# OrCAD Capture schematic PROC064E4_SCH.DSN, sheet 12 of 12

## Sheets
12 05. CAN/RS485/BORD ID INTERFACE: size C; title: CAN/RS485/BOARD ID INTERFACE
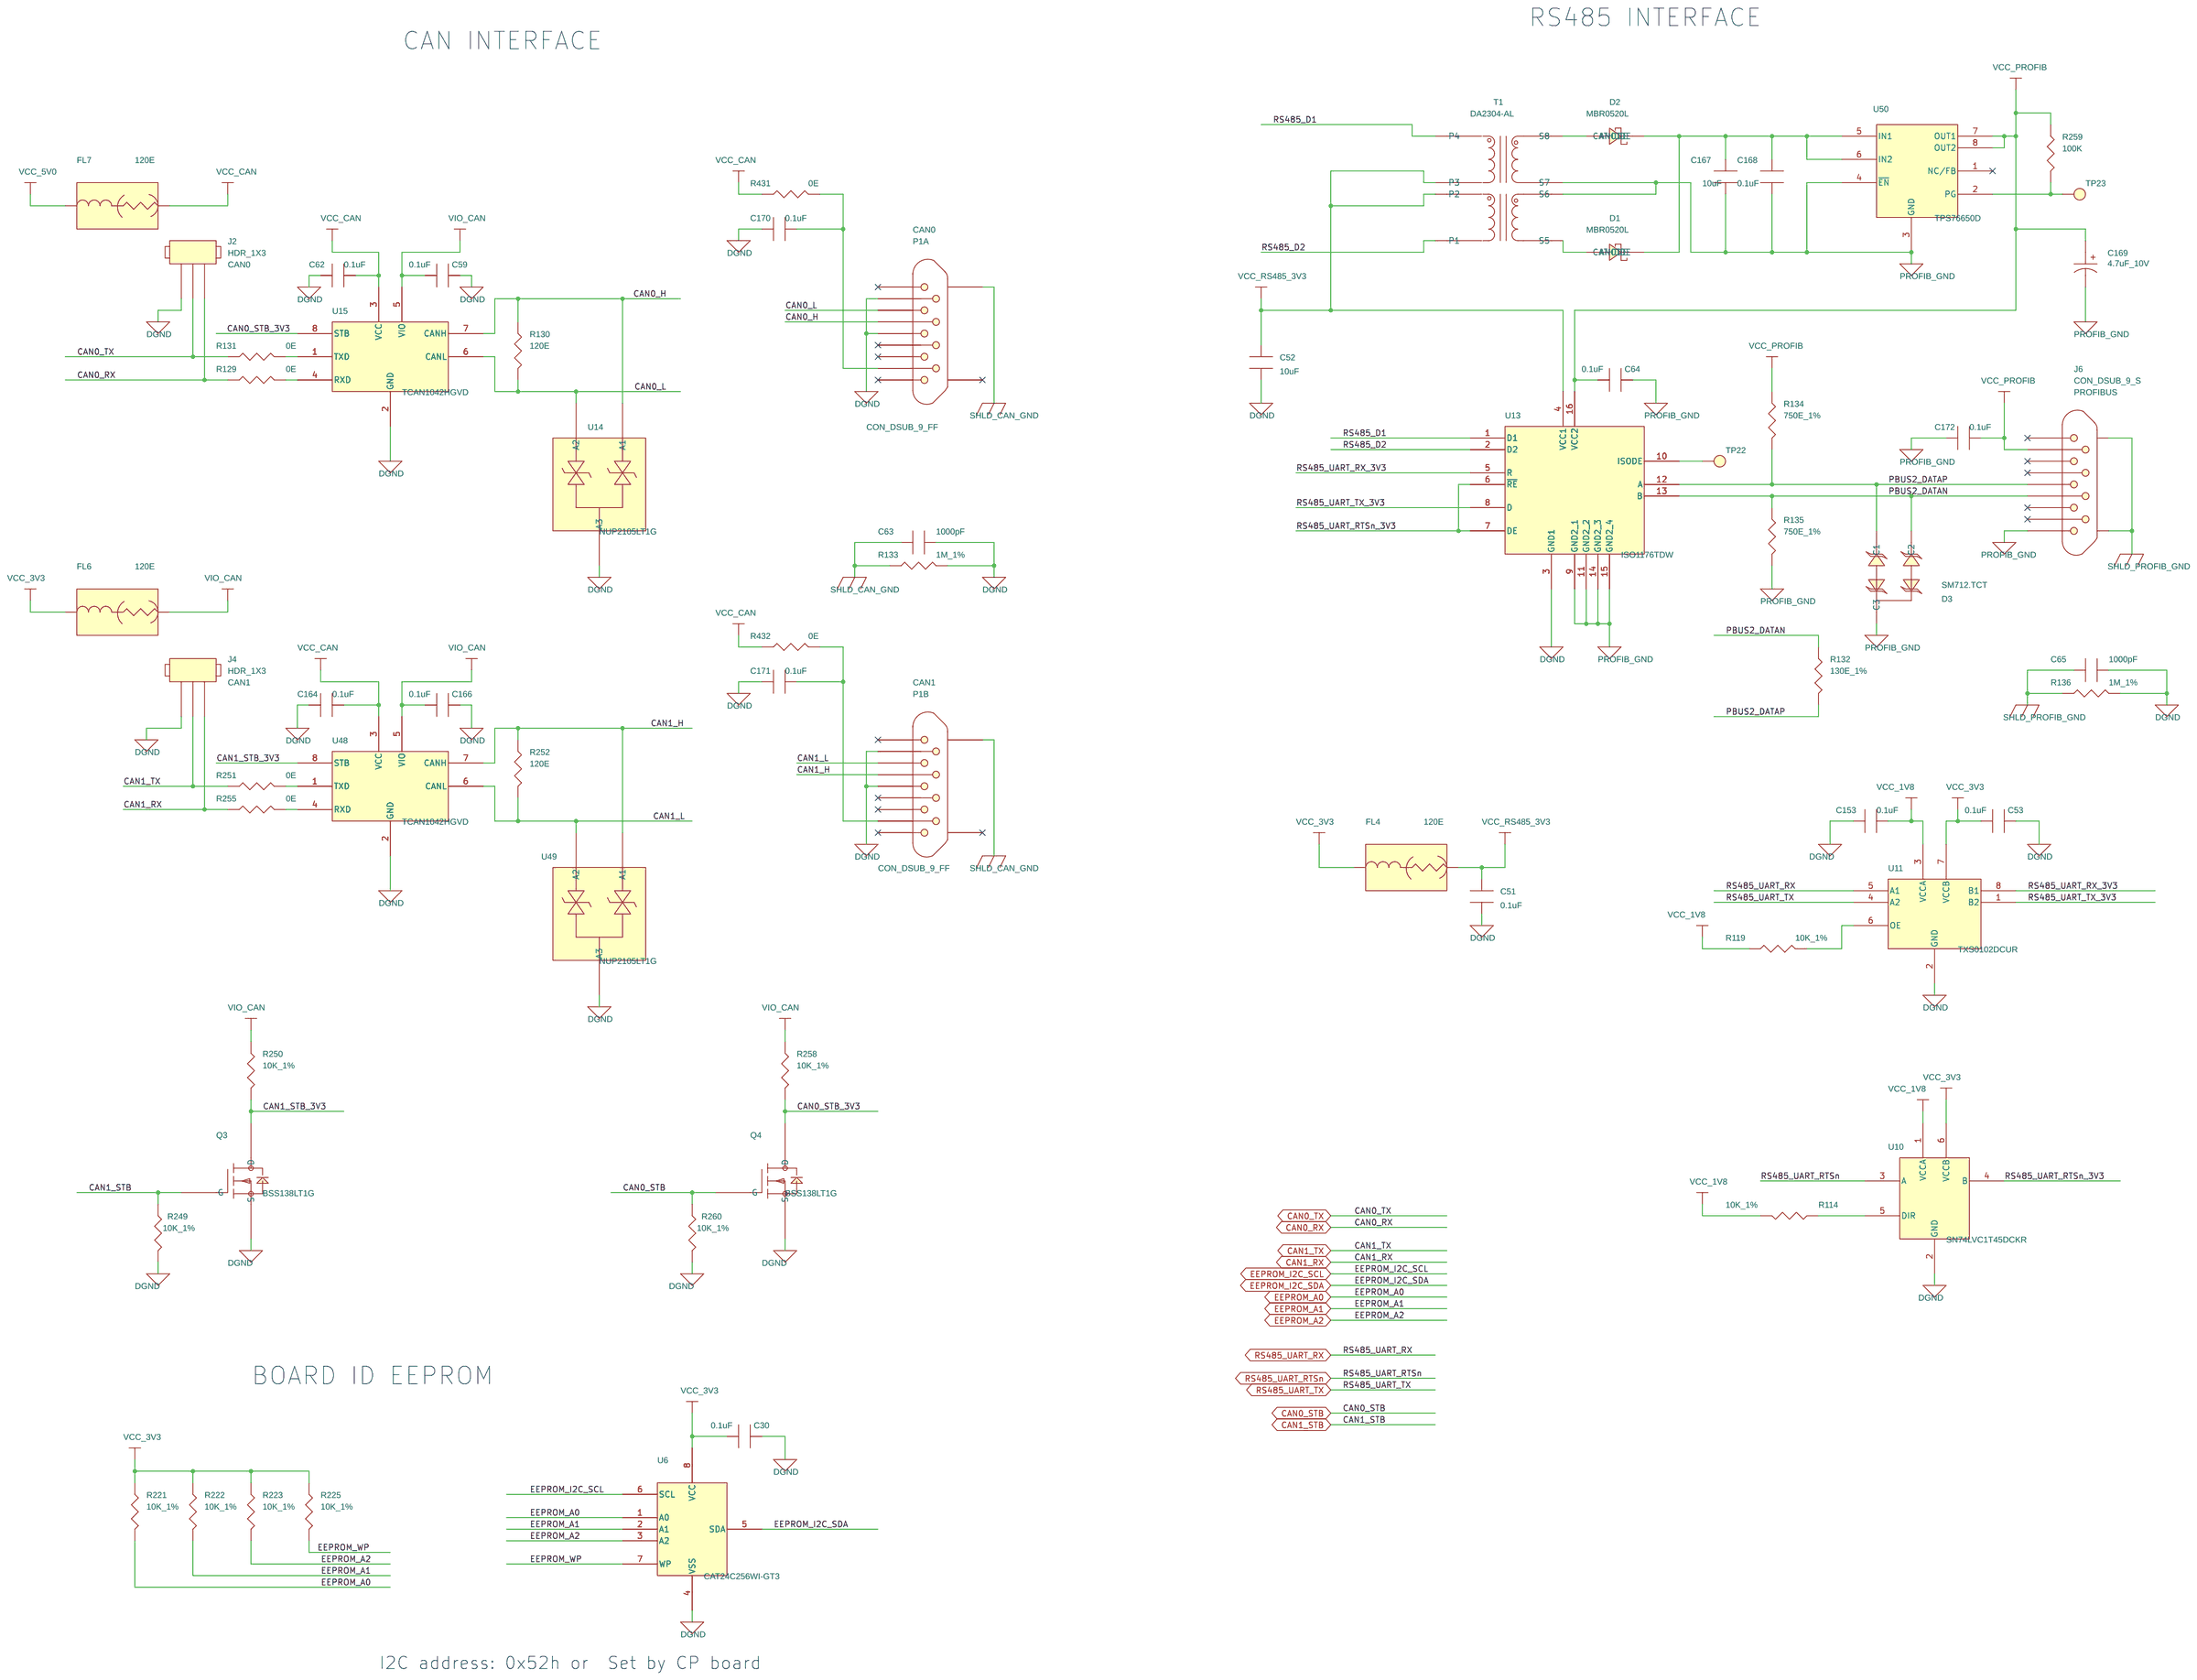
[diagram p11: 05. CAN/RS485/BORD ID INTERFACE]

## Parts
C30  0.1uF  [CAP0402_0-75]
C51  0.1uF  [CAP0402_0-75]
C52  10uF  [CAP0603_1]
C53  0.1uF  [CAP0402_0-75]
C59  0.1uF  [CAP0402_0-75]
C62  0.1uF  [CAP0402_0-75]
C63  1000pF  [CAP1206]
C64  0.1uF  [CAP0402_0-75]
C65  1000pF  [CAP1206]
C153  0.1uF  [CAP0402_0-75]
C164  0.1uF  [CAP0402_0-75]
C166  0.1uF  [CAP0402_0-75]
C167  10uF  [CAP0603_1]
C168  0.1uF  [CAP0402_0-75]
C169  4.7uF_10V  [CAPT3216A_2]
C170  0.1uF  [CAP0402_0-75]
C171  0.1uF  [CAP0402_0-75]
C172  0.1uF  [CAP0402_0-75]
D1  MBR0520L  [DIO_SOD123]
D2  MBR0520L  [DIO_SOD123]
D3  SM712.TCT  [DIO_SOT23_123]
FL4  120E  [EMIFIL_BLM15A_0402_0-6]
FL6  120E  [EMIFIL_BLM15A_0402_0-6]
FL7  120E  [EMIFIL_BLM15A_0402_0-6]
J2  HDR_1X3  [HDR_3X1_100_S_T]
J4  HDR_1X3  [HDR_3X1_100_S_T]
J6  CON_DSUB_9_S  [CON_DB9_D09S33E4GV_S_R_T]
P1  CON_DSUB_9_FF  [CON_DB9_ASUB-277-09_S_R_T_31-6]  (sections A,B)
Q3  BSS138LT1G  [SOT23-123]
Q4  BSS138LT1G  [SOT23-123]
R114  10K_1%  [RES0402_0-5]
R119  10K_1%  [RES0402_0-5]
R129  0E  [RES0402_0-5]
R130  120E  [RES0603]
R131  0E  [RES0402_0-5]
R132  130E_1%  [RES0603]
R133  1M_1%  [RES0402]
R134  750E_1%  [RES0402_0-5]
R135  750E_1%  [RES0402_0-5]
R136  1M_1%  [RES0402]
R221  10K_1%  [RES0402_0-5]
R222  10K_1%  [RES0402_0-5]
R223  10K_1%  [RES0402_0-5]
R225  10K_1%  [RES0402_0-5]
R249  10K_1%  [RES0402_0-5]
R250  10K_1%  [RES0402_0-5]
R251  0E  [RES0402_0-5]
R252  120E  [RES0603]
R255  0E  [RES0402_0-5]
R258  10K_1%  [RES0402_0-5]
R259  100K  [RES0402_0-5]
R260  10K_1%  [RES0402_0-5]
R431  0E  [RES0603_0-75]
R432  0E  [RES0603_0-75]
T1  DA2304-AL  [XFMR8_DA2303-A_320X390_SMD_6]
TP22  TP40_SMD  [TP40_SMD]
TP23  TP40_SMD  [TP40_SMD]
U6  CAT24C256WI-GT3  [SOIC8_1-8]
U10  SN74LVC1T45DCKR  [SC70-6_1-1]
U11  TXS0102DCUR  [VSSOP8_19-68_85X95_0-9]
U13  ISO1176TDW  [SOIC16_W]
U14  NUP2105LT1G  [SOT23-123]
U15  TCAN1042HGVD  [SOIC8_1-8]
U48  TCAN1042HGVD  [SOIC8_1-8]
U49  NUP2105LT1G  [SOT23-123]
U50  TPS76650D  [SOIC8]

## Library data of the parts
C30 C51 C53 C59 C62 C64 C153 C164 C166 C168 C170-C172 = CAP: CAP CERAMIC 0.1uF 25V 10% X5R 0402; Chkd/date: MANIRAJA/210817; Crtd /date: MANIRAJA/210817; Custom_Duty: 15%; Customs_HS_Code: 85322990; Distributor_name: DIGIKEY; Distributor_part_number: 490-5920-1-ND; Footprint Path: Y:\MIS_DATABASE\Library\ALTIUM_TOOL\PCB_FOOTPRINTS\Altium_Footprint_Lib.PcbLib; Height: 0.55MM; Library Path: Y:\MIS_DATABASE\Library\ALTIUM_TOOL\SCHEMATICS_PARTS\MS_DISCRETE_Library.schlib; Mfr_name: MURATA; Mfr_part_number: GRM155R61E104KA87D; Mistral Part No: 120017080016-R; Package: 0402; Part_type: CAPACITORS\CERAMIC; Project: TI_RF_DC CARD; RoHS: RoHS; Temperature: -55°C+85°C; Tolerance: 10%; Voltage: 25V; Wattage: NA; Weight: 11mg; Datasheet: Y:\MIS_DATABASE\DATASHEETS\CAPACITORS\GRM188SERIES.PDF
C52 C167 = CAP: CAP CERAMIC 10uF 25V 20% X5R 0603; Chkd/date: MANIRAJA/130617; Crtd /date: MUDDU/130810; Custom_Duty: 15%; Customs_HS_Code: 85322990; Distributor_name: DIGIKEY; Distributor_part_number: 490-7202-1-ND; Height: 0.90MM; Mfr_name: MURATA; Mfr_part_number: GRM188R61E106MA73D; Mistral Part No: 120010080005-R; Package: 0603; Part_type: CAPACITORS\CERAMIC; Project: PB_BUGBASE; RoHS: RoHS; Temperature: -55°C+85°C; Tolerance: 20%; Voltage: 25V; Wattage: NA; Weight: 6.3mg; Datasheet: Y:\MIS_DATABASE\DATASHEETS\CAPACITORS\MURATA_CMCC.PDF
C63 C65 = CAP: CAP CERAMIC 1000pF 2KV 10% X7R 1206; Chkd/date: SHREESHAIL/291106; Crtd /date: MAZHAR/281106; Custom_Duty: 15%; Customs_HS_Code: 85322990; Distributor_name: DIGIKEY; Distributor_part_number: 478-2956-1-ND; Footprint Path: Y:\MIS_DATABASE\Library\ALTIUM_TOOL\PCB_FOOTPRINTS\Altium_Footprint_Lib.PcbLib; Height: 1.50MM; Library Path: Y:\MIS_DATABASE\Library\ALTIUM_TOOL\SCHEMATICS_PARTS\MS_DISCRETE_Library.schlib; Mfr_name: AVX CORPORATION; Mfr_part_number: 1206GC102KAT1A; Mistral Part No: 120009030147-R; Package: 1206; Part_type: CAPACITORS\CERAMIC; Project: ADR1B; RoHS: RoHS; Temperature: -55°C+125°C; Tolerance: 10%; Voltage: 2KV; Weight: NA; Datasheet: Y:\MIS_DATABASE\DATASHEETS\CAPACITORS\AVX_MLC.PDF
C169 = CAP_POL: CAP TANTALUM 4.7uF 10V 10% ESR 5E A3216; Chkd/date: MANIRAJA/161017; Crtd /date: MAZHAR/080806; Custom_Duty: 15%; Customs_HS_Code: 85322990; Distributor_name: DIGIKEY; Distributor_part_number: 399-3696-1-ND; Height: 1.80MM; Mfr_name: KEMET; Mfr_part_number: T491A475K010AT; Mistral Part No: 120009080027-R; Package: A3216; Part_type: CAPACITORS\TANTALUM; Project: SVDO_RMB_MMA; RoHS: RoHS; Temperature: -55°C+125°C; Tolerance: 10%; Voltage: 10V; Wattage: NA; Weight: 16.2mg; Datasheet: Y:\MIS_DATABASE\DATASHEETS\CAPACITORS\KEMETTANTALUMT491.PDF
D1 D2 = DIODE_SCHOTTKY: DIODE SCHOTTKY 20V 0.5A SOD123; Chkd/date: SHREESHAIL/291106; Crtd /date: MAZHAR/281106; Custom_Duty: 15%; Customs_HS_Code: 85412900; Distributor_name: DIGIKEY; Distributor_part_number: MBR0520LCT-ND; Height: 1.27MM; Mfr_name: FAIRCHILD; Mistral Part No: 130009030205; Package: SOD123; Part_type: DIODE\SCHOTTKY; Project: LTS; Voltage: 20V; Datasheet: Y:\MIS_DATABASE\DATASHEETS\DISCRETES\DIODES\MBR0520L.PDF
D3 = DIODE_SM712_TVS: DIODE TVS ASYMM RS-485V 7/12V SOT23; Chkd/date: SUHAS/061010; Crtd /date: MAZHAR/030210; Custom_Duty: 15%; Customs_HS_Code: 85412900; Distributor_name: DIGIKEY; Distributor_part_number: SM712CT-ND; Height: 1.12MM; Mfr_name: SEMTECH; Mistral Part No: 130010020003-R; Package: SOT23-3; Part_type: DIODE\MISC; Project: OMAPL138; RoHS: Pb-Free; Temperature: -55°C+125°C; Datasheet: Y:\MIS_DATABASE\DATASHEETS\DISCRETES\DIODES\SM712.PDF
FL4 FL6 FL7 = EMIFILTER_IND: FERRITE CHIP 120E 1.3A 0402; Chkd/date: VASANTHA/010117; Crtd /date: CHAITHANYA/150312; Custom_Duty: 24%; Customs_HS_Code: 85437099; Distributor_name: DIGIKEY; Distributor_part_number: 490-5203-1-ND; Footprint Path: Y:\MIS_DATABASE\Library\ALTIUM_TOOL\PCB_FOOTPRINTS\Altium_Footprint_Lib.PcbLib; Height: 0.55MM; Library Path: Y:\MIS_DATABASE\Library\ALTIUM_TOOL\SCHEMATICS_PARTS\MS_FILTER_Library.schlib; Mfr_name: MURATA; Mfr_part_number: BLM15PD121SN1; Mistral Part No: 130012030043-R; Package: 0402; Part_type: MISC\FILTER; Project: GEN_3-8; RoHS: RoHS; Temperature: -55°C+125°C; Tolerance: 25%; Voltage: NA; Wattage: NA; Weight: 0.65mg; Datasheet: Y:\MIS_DATABASE\DATASHEETS\DISCRETES\INDUCTORS\BLM18K-SERIES.PDF
J2 = HEADER_3X1: HDR 1X3 2.54MM PITCH ST TH; Chkd/date: VASANTHA/290616; Crtd /date: VASANTHA/290616; Custom_Duty: 15%; Customs_HS_Code: 85322990; Distributor_name: DIGIKEY; Distributor_part_number: 609-3471-ND; Height: 8.58MM; Mfr_name: FCI; Mfr_part_number: 68001-403HLF; Mistral Part No: 150016060025-R; Package: THRU-HOLE; Part_type: CONNECTOR\HEADERS; Project: IKEYP; RoHS: RoHS; TEXT: CAN0; Temperature: -40°C+105°C; Tolerance: NA; Voltage: NA; Wattage: NA; Weight: NA; Datasheet: Y:\MIS_DATABASE\DATASHEETS\CONNECTORS\68000.PDF
J4 = HEADER_3X1: HDR 1X3 2.54MM PITCH ST TH; Chkd/date: VASANTHA/290616; Crtd /date: VASANTHA/290616; Custom_Duty: 15%; Customs_HS_Code: 85322990; Distributor_name: DIGIKEY; Distributor_part_number: 609-3471-ND; Height: 8.58MM; Mfr_name: FCI; Mfr_part_number: 68001-403HLF; Mistral Part No: 150016060025-R; Package: THRU-HOLE; Part_type: CONNECTOR\HEADERS; Project: IKEYP; RoHS: RoHS; TEXT: CAN1; Temperature: -40°C+105°C; Tolerance: NA; Voltage: NA; Wattage: NA; Weight: NA; Datasheet: Y:\MIS_DATABASE\DATASHEETS\CONNECTORS\68000.PDF
J6 = CON_D9F_RT_TH: CON DSUB 9POS FEMALE RT TH; Chkd/date: JEBRAN/300915; Crtd /date: JEBRAN/300915; Custom_Duty: 24%; Customs_HS_Code: 85369090; Distributor_name: DIGIKEY; Distributor_part_number: 609-1486-ND; Height: 12.58MM; Mfr_name: FCI; Mfr_part_number: D09S33E4GV00LF; Mistral Part No: 150015100004; Package: THRU HOLE; Part_type: CONNECTOR\DSUB; Project: DEBEL_GCS; TEXT: PROFIBUS; Temperature: NA; Tolerance: NA; Voltage: NA; Wattage: NA; Weight: NA; Datasheet: Y:\MIS_DATABASE\DATASHEETS\CONNECTORS\D09S33E4GV00LF.PDF
P1 = CON_DSUB_9_F-F: CON DSUB 9POS FEMALE OVER FEMALE RT TH; Chkd/date: MANIRAJA/110917; Crtd /date: MANIRAJA/110917; Custom_Duty: 24%; Customs_HS_Code: 85369090; Distributor_name: DIGIKEY; Distributor_part_number: AE10960-ND; Height: 31.55MM; Mfr_name: ASSMANN; Mfr_part_number: ASUB-277-09TP26; Mistral Part No: 150017090009-R; Package: THRU-HOLE; Part_type: CONNECTOR\DSUB; Project: TI_SVB_MAXWELL_FMB; RoHS: RoHS; TEXT1: CAN0; Temperature: -55°C+105°C; Tolerance: NA; Voltage: NA; Wattage: NA; Weight: NA; Datasheet: Y:\MIS_DATABASE\DATASHEETS\CONNECTORS\ASUB-277-SER.PDF
Q3 Q4 = MOSFET_BSS138LT1G: IC MOSFET N-CHANNEL 50V, SOT23-3; Chkd/date: VASANTHA/150416; Crtd /date: JEBRAN/060416; Custom_Duty: 15%; Customs_HS_Code: 85423100; Distributor_name: MOUSER; Distributor_part_number: 863-BSS138LT1G; Height: 1.11MM; Mfr_name: ON SEMICONDUCTOR; Mistral Part No: 142016040001-R; Package: SOT23-3; Part_type: ICS\POWER\MOSFET; Project: LRDE_ABCM; RoHS: RoHS; Temperature: -55°C+150°C; Tolerance: NA; Voltage: 50V; Wattage: NA; Weight: NA; Datasheet: Y:\MIS_DATABASE\DATASHEETS\DISCRETES\TRANSISTORS_FETS\BSS138LT1G.PDF
R114 R119 R221-R223 R225 R249 R250 R258 R260 = RESISTOR: RES 10K 1/16W 1% 0402; Chkd/date: VASANTHA/201216; Crtd /date: GEETHA/290506; Custom_Duty: 15%; Customs_HS_Code: 85332119; Distributor_name: DIGIKEY; Distributor_part_number: 311-10.0KLRTR-ND; Footprint Path: Y:\MIS_DATABASE\Library\ALTIUM_TOOL\PCB_FOOTPRINTS\Altium_Footprint_Lib.PcbLib; Height: 0.40MM; Library Path: Y:\MIS_DATABASE\Library\ALTIUM_TOOL\SCHEMATICS_PARTS\MS_DISCRETE_Library.schlib; Mfr_name: YAGEO AMERICA; Mfr_part_number: RC0402FR-0710KL; Mistral Part No: 110009030220-P; Package: 0402; Part_type: RESISTORS\FIXED; Project: VOCERA; RoHS: Pb-Free; Temperature: -55°C+155°C; Tolerance: 1%; Voltage: NA; Wattage: 1/16W; Weight: 0.65mg; Datasheet: Y:\MIS_DATABASE\DATASHEETS\RESISTORS\YAGEO-RC0402.PDF
R129 R131 R251 R255 = RESISTOR: RES 0E 1/16W 0402; Chkd/date: VASANTHA/201216; Crtd /date: MUDDU/190810; Custom_Duty: 15%; Customs_HS_Code: 85332119; Distributor_name: DIGIKEY; Distributor_part_number: 541-0.0JCT-ND; Footprint Path: Y:\MIS_DATABASE\Library\ALTIUM_TOOL\PCB_FOOTPRINTS\Altium_Footprint_Lib.PcbLib; Height: 0.40MM; Library Path: Y:\MIS_DATABASE\Library\ALTIUM_TOOL\SCHEMATICS_PARTS\MS_DISCRETE_Library.schlib; Mfr_name: VISHAY; Mfr_part_number: CRCW04020000Z0ED; Mistral Part No: 110010080019-P; Package: 0402; Part_type: RESISTORS\FIXED; Project: PB_BUGBASE; RoHS: Pb-Free; Temperature: -55°C+155°C; Tolerance: NA; Voltage: NA; Wattage: 1/16W; Weight: 0.65g/1000pcs; Datasheet: Y:\MIS_DATABASE\DATASHEETS\RESISTORS\CRCW0603.PDF
R130 R252 = RESISTOR: RES 120E 1/10W 5% 0603; Alternate_mfr_name_A: VISHAY; Alternate_mfr_name_B: YAGEO; Alternate_mfr_name_D: ROHM; Alternate_mfr_part_number_A: CRCW0603120RJNEA; Alternate_mfr_part_number_B: RC0603JR-07120RL; Alternate_mfr_part_number_D: MCR03EZPJ121; Chkd/date: MAZHAR/310508; Crtd /date: USMAN/290508; Custom_Duty: 15%; Customs_HS_Code: 85332119; Distributor_name: DIGIKEY; Distributor_name_A: DIGIKEY; Distributor_name_B: DIGIKEY; Distributor_name_D: DIGIKEY; Distributor_part_number: P120GCT-ND; Distributor_part_number_A: 541-120GCT-ND; Distributor_part_number_B: 311-120GRCT-ND; Distributor_part_number_D: RHM120GCT-ND; Height: 0.55MM; Mfr_name: PANASONIC-ECG; Mfr_part_number: ERJ-3GEYJ121V; Mistral Part No: 110009030254-R; Package: 0603; Part_type: RESISTORS\FIXED; Project: REVA-IBMS; Remarks: Alternate added, BAVISH/130111, Ref : Y:\MIS_DATABASE\DATASHEETS\RESISTORS\CRCW0603.PDF; RoHS: RoHS; Temperature: -55°C+155°C; Tolerance: 5%; Voltage: NA; Wattage: 1/10W; Weight: 2/1000g; Datasheet: Y:\MIS_DATABASE\DATASHEETS\RESISTORS\PAN-ERJ-3GE.PDF
R132 = RESISTOR: RES 130E 1/10W 1% 0603; Chkd/date: BAVISH/030811; Crtd /date: CHAITHANYA/010811; Custom_Duty: 15%; Customs_HS_Code: 85332119; Distributor_name: DIGIKEY; Distributor_part_number: 541-130HCT-ND; Height: 0.50MM; Mfr_name: VISHAY; Mfr_part_number: CRCW0603130RFKEA; Mistral Part No: 110011080008-R; Package: 0603; Part_type: RESISTORS\FIXED; Project: ACRO_DM3730; RoHS: RoHS; Temperature: -55°C+155°C; Tolerance: 1%; Voltage: NA; Wattage: 1/10W; Weight: 5.5mg; Datasheet: Y:\MIS_DATABASE\DATASHEETS\RESISTORS\CRCW0603.PDF
R133 R136 = RESISTOR: RES 1M 1/16W 1% 0402; Chkd/date: VASANTHA/200614; Crtd /date: NAVEED/170614; Custom_Duty: 15%; Customs_HS_Code: 85332119; Distributor_name: DIGIKEY; Distributor_part_number: RMCF0402FT1M00CT-ND; Footprint Path: Y:\MIS_DATABASE\Library\ALTIUM_TOOL\PCB_FOOTPRINTS\Altium_Footprint_Lib.PcbLib; Height: 0.40MM; Library Path: Y:\MIS_DATABASE\Library\ALTIUM_TOOL\SCHEMATICS_PARTS\MS_DISCRETE_Library.schlib; Mfr_name: STACKPOLE ELECTRONICS; Mfr_part_number: RMCF0402FT1M00; Mistral Part No: 110014060045-R; Package: 0402; Part_type: RESISTORS\FIXED; Project: AEGIS_POM; RoHS: RoHS; Temperature: -55°C+155°C; Tolerance: 1%; Voltage: NA; Wattage: 1/16W; Weight: 0.57mg; Datasheet: Y:\MIS_DATABASE\DATASHEETS\RESISTORS\RMCF-SERIES1.PDF
R134 R135 = RESISTOR: RES 750E 1/16W 1% 0402; Chkd/date: VASANTHA/201216; Crtd /date: MUDDU/160710; Custom_Duty: 15%; Customs_HS_Code: 85332119; Distributor_name: DIGIKEY; Distributor_part_number: 541-750LCT-ND; Footprint Path: Y:\MIS_DATABASE\Library\ALTIUM_TOOL\PCB_FOOTPRINTS\Altium_Footprint_Lib.PcbLib; Height: 0.40MM; Library Path: Y:\MIS_DATABASE\Library\ALTIUM_TOOL\SCHEMATICS_PARTS\MS_DISCRETE_Library.schlib; Mfr_name: VISHAY; Mfr_part_number: CRCW0402750RFKED; Mistral Part No: 110010070071-P; Package: 0402; Part_type: RESISTORS\FIXED; Project: CENTAURUS; RoHS: Pb-Free; Temperature: -55°C+155°C; Tolerance: 1%; Voltage: NA; Wattage: 1/16W; Weight: 0.65g/1000pcs; Datasheet: Y:\MIS_DATABASE\DATASHEETS\RESISTORS\CRCW0603.PDF
R259 = RESISTOR: RES 100K 1/16W 5% 0402; Chkd/date: VASANTHA/061216; Crtd /date: BAVISH/010611; Custom_Duty: 15%; Customs_HS_Code: 85332119; Distributor_name: DIGIKEY; Distributor_part_number: 541-100KJCT-ND; Height: 0.40MM; Mfr_name: VISHAY; Mfr_part_number: CRCW0402100KJNED; Mistral Part No: 110011060002-R; Package: 0402; Part_type: RESISTORS\FIXED; Project: AM4515_EVM_LCD; RoHS: RoHS; Temperature: -55°C+155°C; Tolerance: 5%; Voltage: NA; Wattage: 1/16W; Weight: 0.65mg; Datasheet: Y:\MIS_DATABASE\DATASHEETS\RESISTORS\CRCW0603.PDF
R431 R432 = RESISTOR: RES JUMPER 0E 1/10W 0603; Chkd/date: MANIRAJA/051217; Crtd /date: BAVISH/180211; Custom_Duty: 15%; Customs_HS_Code: 85332119; Distributor_name: DIGIKEY; Distributor_part_number: 311-0.0GRCT-ND; Height: 0.55MM; Mfr_name: YAGEO AMERICA; Mfr_part_number: RC0603JR-070RL; Mistral Part No: 110011020013-R; Package: 0603; Part_type: RESISTORS\FIXED; Project: KENNEL; RoHS: RoHS; Temperature: -55°C+155°C; Tolerance: NA; Voltage: NA; Wattage: 1/10W; Weight: 24mg; Datasheet: Y:\MIS_DATABASE\DATASHEETS\RESISTORS\RC0603.PDF
T1 = TRANS_DA2303-AL: TRANSFORMER POWER SMD; Chkd/date: MANIRAJA/150917; Crtd /date: VASANTHA/071014; Distributor_name: NA; Distributor_part_number: NA; Height: 5.97MM; Mfr_name: COIL CRAFT; Mistral Part No: 130014100010-R; Package: SMD; Part_type: TRANSFORMER; Project: AEGIS_POM; RoHS: RoHS; Temperature: -40°C+125°C; Tolerance: NA; Voltage: NA; Wattage: NA; Weight: 1g; Datasheet: Y:\MIS_DATABASE\DATASHEETS\ICS\MISC\DA2303-AL.PDF
TP22 TP23 = TESTPOINT: TESTPOINT CIR 40 SMD; Chkd/date: MAZHAR/190505; Crtd /date: MAZHAR/190505; Distributor_name: NA; Distributor_part_number: NA; Footprint Path: Y:\MIS_DATABASE\Library\ALTIUM_TOOL\PCB_FOOTPRINTS\Altium_Footprint_Lib.PcbLib; Height: NA; Library Path: Y:\MIS_DATABASE\Library\ALTIUM_TOOL\SCHEMATICS_PARTS\MS_DISCRETE_Library.schlib; MECHANICAL 3D STEP FILE: NA; Mfr_name: LOCAL; Mistral Part No: 130009030933; Package: SMD; Project: RAINIER-3; RoHS: NA; Temperature: NA; Tolerance: NA; Voltage: NA; Wattage: NA; Weight: NA; Datasheet: NA
U6 = CAT24C256WI-GT3_SOIC8: IC 256K I2C CMOS SERIAL EEPROM SOIC8; Chkd/date: MANIRAJA/130617; Crtd /date: MUDDU/270510; Custom_Duty: 15%; Customs_HS_Code: 85423100; Distributor_name: DIGIKEY; Distributor_part_number: CAT24C256WI-GT3-ND; Height: 1.75MM; Mfr_name: ON SEMICONDUCTOR; Mistral Part No: 141110050004-R; Package: SOIC8; Part_type: ICS\DIGITAL\MEMORY; Project: CENTAURUS; RoHS: RoHS; Temperature: -40°C+85°C; Tolerance: NA; Voltage: NA; Wattage: NA; Weight: 540mg; Datasheet: Y:\MIS_DATABASE\DATASHEETS\ICS\MEMORY\CAT24C256WI.PDF
U10 = SN74LVC1T45DCKR_SC70-6: IC BUS TRANSCEIVER TRI-STATE SC70-6; Chkd/date: VASANTHA/221216; Crtd /date: MUDDU/180510; Custom_Duty: 15%; Customs_HS_Code: 85423100; Distributor_name: DIGIKEY; Distributor_part_number: 296-16844-1-ND; Height: 1.10MM; Mfr_name: TEXAS INSTRUMENTS; Mistral Part No: 141010050007-R; Package: SC70-6; Part_type: ICS\DIGITAL\COMBINATIONAL; Project: ICD_DFS; RoHS: Sb/ Br FREE; Temperature: -40°C+85°C; Tolerance: NA; Voltage: NA; Wattage: NA; Weight: 2.5mg; Datasheet: Y:\MIS_DATABASE\DATASHEETS\ICS\DIGITAL\BUSTRANSCEIVER\SN74LVC1T45DCKR.PDF
U11 = TXS0102DCUR_VSSOP8: IC 2BIT BI-DIR VOLTAGE-LEVEL TRANSLATOR US8(VSSOP8); Chkd/date: MANIRAJA/130617; Crtd /date: SHREESHAIL/190108; Custom_Duty: 15%; Customs_HS_Code: 85423100; Distributor_name: DIGIKEY; Distributor_part_number: 296-21931-1-ND; Footprint Path: Y:\MIS_DATABASE\Library\ALTIUM_TOOL\PCB_FOOTPRINTS\Altium_Footprint_Lib.PcbLib; Height: 0.90MM; Library Path: Y:\MIS_DATABASE\Library\ALTIUM_TOOL\SCHEMATICS_PARTS\MS_MISCINTERFACE_Library.schlib; Mfr_name: TEXAS INSTRUMENTS; Mistral Part No: 141009030376-R; Package: US8; Part_type: ICS\INTERFACE\LEVEL TRANSLATOR; Project: SD_WATERLOO; RoHS: RoHS; Temperature: -40°C+85°C; Tolerance: NA; Voltage: NA; Wattage: NA; Weight: 9.6mg; Datasheet: Y:\MIS_DATABASE\DATASHEETS\ICS\INTERFACE\TXS0102.PDF
U13 = ISO1177DW_SOIC16: IC ISOLATED RS-485 PROFIBUS TRANSCEIVER SOIC16; Chkd/date: NAVEED/22014; Crtd /date: VASANTHA/111014; Custom_Duty: 15%; Customs_HS_Code: 85423100; Distributor_name: DIGIKEY; Distributor_part_number: 296-28103-5-ND; Height: 2.65MM; Mfr_name: TEXAS INSTRUMENTS; Mistral Part No: 141014100007-R; Package: SOIC16; Part_type: ICS\INTERFACE\LINE DRIVER; Project: AEGIS_POM; RoHS: RoHS; Temperature: -40°C+85°C; Tolerance: NA; Voltage: NA; Wattage: NA; Weight: NA; Datasheet: Y:\MIS_DATABASE\DATASHEETS\ICS\INTERFACE\ISO1176TDW.PDF
U14 U49 = NUP2105LT1G_SOT23-3: IC DUAL LINE CAN BUS PROTECTOR SOT23-3; Chkd/date: MAZHAR/260508; Crtd /date: USMAN/120508; Custom_Duty: 15%; Customs_HS_Code: 85412900; Distributor_name: DIGIKEY; Distributor_part_number: NUP2105LT1GOSCT-ND; Height: 1.11MM; Mfr_name: ON SEMICONDUCTOR; Mistral Part No: 130009030137-P; Package: SOT23-3; Part_type: DIODE\MISC; Project: REVA-IBMS; RoHS: Pb-Free; Datasheet: Y:\MIS_DATABASE\DATASHEETS\DISCRETES\DIODES\NUP2105LT.PDF
U15 U48 = TCAN1042HGVD_SOIC8: IC FAULT PROTECTED CAN TRANSCEIVER WITH CAN FD SOIC8; Chkd/date: MANIRAJA/030717; Crtd /date: MANIRAJA/030717; Custom_Duty: 15%; Customs_HS_Code: 85423100; Distributor_name: DIGIKEY; Distributor_part_number: 296-43979-5-ND; Footprint Path: Y:\MIS_DATABASE\Library\ALTIUM_TOOL\PCB_FOOTPRINTS\Altium_Footprint_Lib.PcbLib; Height: 1.75MM; Library Path: Y:\MIS_DATABASE\Library\ALTIUM_TOOL\SCHEMATICS_PARTS\MS_TELECOM_Library.schlib; Mfr_name: TEXAS INSTRUMENTS; Mistral Part No: 143017070001-R; Package: SOIC8; Part_type: ICS\TELECOM\TRANSCEIVER; Project: TI_SVB_CONTROLLER CARD; RoHS: RoHS; Temperature: -55°C+125°C; Tolerance: NA; Voltage: NA; Wattage: NA; Weight: 540mg; Datasheet: Y:\MIS_DATABASE\DATASHEETS\ICS\DIGITAL\BUSTRANSCEIVER\TCAN1042.PDF
U50 = TPS766_SOIC8: IC LDO VOLTAGE REGULATOR 5V 250mA SOIC8; Chkd/date: RAGESH/201010; Crtd /date: MAZHAR/030210; Custom_Duty: 15%; Customs_HS_Code: 85423100; Distributor_name: DIGIKEY; Distributor_part_number: 296-2730-5-ND; Height: 1.75MM; Mfr_name: TEXAS INSTRUMENTS; Mistral Part No: 142010020006-R; Part_type: ICS\POWER\VOLTAGE REGULATOR; Project: OMAPL138; RoHS: RoHS; Temperature: -40°C+125°C; Weight: NA; Datasheet: Y:\MIS_DATABASE\DATASHEETS\MISC\REGULATORS\TPS766.PDF

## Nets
DGND: C30.2 C51.1 C52.2 C53.2 C59.2 C62.2 C63.2 C65.2 C153.2 C164.2 C166.2 C170.2 C171.2 J2.1 J4.1 P1.A3 P1.A6 P1.B3 P1.B6 Q3.2(S) Q4.2(S) R133.2 R136.2 R249.1 R260.1 U6.4(VSS) U10.2(GND) U11.2(GND) U13.3(GND1) U14.3(A3) U15.2(GND) U48.2(GND) U49.3(A3) ; also on sheet 4 5 6 7 8 9 11
VCC_1V8: C153.1 R114.1 R119.1 U10.1(VCCA) U11.3(VCCA) ; also on sheet 4 5 6 7 8 11
VCC_3V3: C30.1 C53.1 FL4.1 FL6.1 R221.1 R222.1 R223.1 R225.1 U6.8(VCC) U10.6(VCCB) U11.7(VCCB) ; also on sheet 4 5 6 7 8 9 11
VCC_5V0: FL7.1 ; also on sheet 4 11
VCC_CAN: C62.1 C164.1 FL7.2 R431.1 R432.1 U15.3(VCC) U48.3(VCC)
VCC_PROFIB: C64.1 C169.1 C172.1 J6.6 R134.1 R259.1 U13.16(VCC2) U50.7(OUT1) U50.8(OUT2)
VCC_RS485_3V3: C51.2 C52.1 FL4.2 T1.2(P2) T1.3(P3) U13.4(VCC1)
CAN0_H: P1.A7 R130.1 U14.1(A1) U15.7(CANH)
CAN0_L: P1.A2 R130.2 U14.2(A2) U15.6(CANL)
CAN0_RX: J2.3 R129.1 ; also on sheet 4
CAN0_STB: Q4.1(G) R260.2 ; also on sheet 4
CAN0_STB_3V3: Q4.3(D) R258.2 U15.8(STB)
CAN0_TX: J2.2 R131.1 ; also on sheet 4
CAN1_H: P1.B7 R252.1 U48.7(CANH) U49.1(A1)
CAN1_L: P1.B2 R252.2 U48.6(CANL) U49.2(A2)
CAN1_RX: J4.3 R255.1 ; also on sheet 4
CAN1_STB: Q3.1(G) R249.2 ; also on sheet 4
CAN1_STB_3V3: Q3.3(D) R250.2 U48.8(STB)
CAN1_TX: J4.2 R251.1 ; also on sheet 4
EEPROM_A0: R221.2 U6.1(A0) ; also on sheet 4
EEPROM_A1: R222.2 U6.2(A1) ; also on sheet 4
EEPROM_A2: R223.2 U6.3(A2) ; also on sheet 4
EEPROM_I2C_SCL: U6.6(SCL) ; also on sheet 4
EEPROM_I2C_SDA: U6.5(SDA) ; also on sheet 4
EEPROM_WP: R225.2 U6.7(WP)
PBUS2_DATAN: D3.2(C2) J6.8 R132.1 R135.1 U13.13(B)
PBUS2_DATAP: D3.1(C1) J6.3 R132.2 R134.2 U13.12(A)
PROFIB_GND: C64.2 C167.1 C168.1 C169.2 C172.2 D3.3(C3) J6.5 R135.2 T1.6(S6) T1.7(S7) U13.9(GND2_1) U13.11(GND2_2) U13.14(GND2_3) U13.15(GND2_4) U50.3(GND) U50.4(~{EN})
RS485_D1: T1.4(P4) U13.1(D1)
RS485_D2: T1.1(P1) U13.2(D2)
RS485_UART_RTSn: U10.3(A) ; also on sheet 4
RS485_UART_RTSn_3V3: U10.4(B) U13.6(~{RE}) U13.7(DE)
RS485_UART_RX: U11.5(A1) ; also on sheet 4
RS485_UART_RX_3V3: U11.8(B1) U13.5(R)
RS485_UART_TX: U11.4(A2) ; also on sheet 4
RS485_UART_TX_3V3: U11.1(B2) U13.8(D)
SHLD_CAN_GND: C63.1 P1.SH1 P1.SH3 R133.1
SHLD_PROFIB_GND: C65.1 J6.10 J6.11 R136.1
VIO_CAN: C59.1 C166.1 FL6.2 R250.1 R258.1 U15.5(VIO) U48.5(VIO)
N16806380: R259.2 TP23.1(TP) U50.2(PG)
N16806418: C167.2 C168.2 D1.1(CATHODE) D2.1(CATHODE) U50.5(IN1) U50.6(IN2)
N16806448: D1.2(ANODE) T1.5(S5)
N16806482: TP22.1(TP) U13.10(ISODE)
N16806647: D2.2(ANODE) T1.8(S8)
N16928128: C170.1 P1.A9 R431.2
N16928596: C171.1 P1.B9 R432.2
N17019519: R119.2 U11.6(OE)
N17203309: R131.2 U15.1(TXD)
N17203330: R129.2 U15.4(RXD)
N17203882: R255.2 U48.4(RXD)
N17203885: R251.2 U48.1(TXD)
N17275254: R114.2 U10.5(DIR)

Not connected (* = marked no-connect by the designer): J6 1* 2* 4* 7* 9*; P1 A1* A4* A5* A8* B1* B4* B5* B8* SH2* SH4*; U50 1(NC/FB)*

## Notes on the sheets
sheet 12
- RS485 INTERFACE
- CAN INTERFACE
- BOARD ID EEPROM
- I2C address: 0x52h or  Set by CP board
